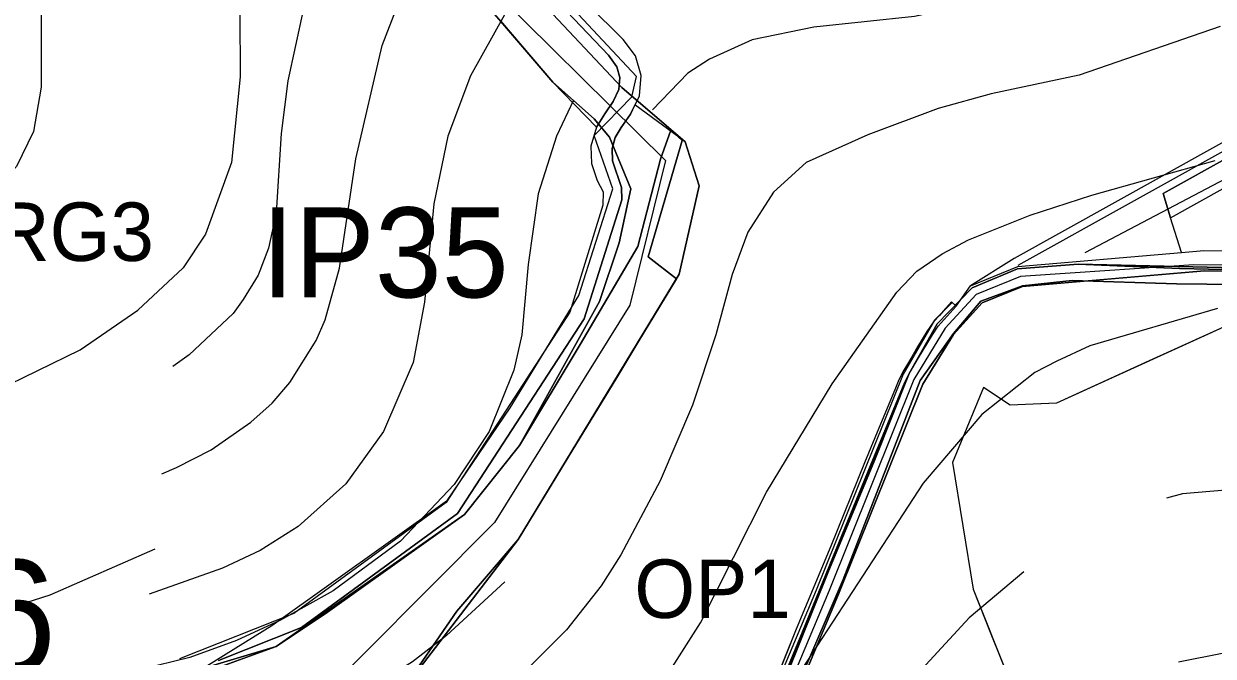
# Model space of a CAD drawing. Extents: x -1900516 to -575031, y -3809306 to -1157387.
# Drawn here: x -579252.3 to -578987.9, y -1159438.2 to -1159297.6 of the extents above; entities that cross this region are included whole.
import ezdxf

# ---------------------------------------------------------------- set-up
doc = ezdxf.new("R2010")
doc.units = 0
for name, color, linetype in [('01_PARCELY_NÁVRH_PC', 7, 'Continuous'), ('01_PARCELY_NÁVRH_VHO', 7, 'Continuous'), ('01_PARCELY_NÁVRH_ŽP', 7, 'Continuous'), ('01_VRSTEVNICE', 7, 'Continuous'), ('02_KULTURY STAV', 7, 'Continuous'), ('03_PC_NÁVRH', 7, 'Continuous'), ('03_PC_OBJEKTY_NÁVRH', 7, 'Continuous'), ('03_PC_POPIS_NÁVRH', 7, 'Continuous'), ('04_ZPF_OP_ORGAN', 7, 'Continuous'), ('05_VHO_PŘÍKOP_NÁVRH', 7, 'Continuous'), ('06_ÚSES_BC', 7, 'Continuous'), ('06_ÚSES_IP', 7, 'Continuous')]:
    doc.layers.add(name, color=color, linetype=linetype)

msp = doc.modelspace()

# ---------------------------------------------------------------- linework, layer by layer
at = {"layer": '01_PARCELY_NÁVRH_PC'}
for points in [[(-579209.05, -1159439.13), (-579190.58, -1159431.78), (-579173.22, -1159419.14), (-579155.86, -1159406.49), (-579127.75, -1159363.22), (-579119.37, -1159336.76), (-579119.42, -1159333.98), (-579121.41, -1159328.05), (-579121.51, -1159325.32), (-579120.84, -1159322.86), (-579119.5, -1159320.68), (-579117.45, -1159317.67), (-579115.47, -1159313.61), (-579115.1, -1159309.07), (-579116.34, -1159304.73), (-579119.1, -1159301.09), (-579150.26, -1159270.13)], [(-579153.05, -1159272.27), (-579122.3, -1159304.59), (-579120.47, -1159307.14), (-579119.83, -1159309.54), (-579120.01, -1159312.2), (-579121.28, -1159314.87), (-579123.13, -1159317.62), (-579125.03, -1159320.58), (-579126.23, -1159324.78), (-579126.14, -1159328.62), (-579124.85, -1159332.45), (-579123.48, -1159334.93), (-579123.57, -1159337.94), (-579130.95, -1159361.72), (-579158.44, -1159404.04), (-579192.28, -1159428.69), (-579217.66, -1159438.78)], [(-578954.52, -1159306.57), (-579032.13, -1159349.74), (-579041.89, -1159355.85), (-579031.32, -1159351.56), (-578994.97, -1159348.41), (-578997.37, -1159340.71), (-578999.05, -1159335.34), (-578952.82, -1159309.63)], [(-579084.53, -1159445.74), (-579079.22, -1159432.79), (-579071.64, -1159414.28), (-579061.79, -1159390.22), (-579056.48, -1159377.27), (-579055.45, -1159375.3), (-579053.4, -1159371.87), (-579052.38, -1159370.15), (-579051.36, -1159368.43), (-579050.33, -1159366.71), (-579049.01, -1159364.85), (-579046.35, -1159361.87), (-579045.01, -1159360.38), (-579041.89, -1159355.85), (-579031.32, -1159351.56), (-578994.97, -1159348.41), (-578990.02, -1159347.98), (-578977.69, -1159348.14)], [(-578680.53, -1159438.83), (-578690.19, -1159436.04), (-578719.21, -1159428.39), (-578740.5, -1159423.22), (-578800.71, -1159407.93), (-578802.57, -1159407.45), (-578816, -1159402.88), (-578834.08, -1159395.96), (-578841.47, -1159393.66), (-578845.51, -1159391.77), (-578865.03, -1159378.15), (-578869.94, -1159374.29), (-578878.12, -1159369.12), (-578887.02, -1159365.74), (-578913.36, -1159358.64), (-578960.86, -1159353.66), (-578977.85, -1159352.64), (-578989.86, -1159352.48), (-579030.26, -1159355.98), (-579039.25, -1159359.63), (-579045.66, -1159366.64), (-579052.43, -1159377.7), (-579071.21, -1159424.42), (-579081.08, -1159447.93)]]:
    msp.add_lwpolyline(points, dxfattribs=at)
at = {"layer": '01_PARCELY_NÁVRH_VHO'}
msp.add_lwpolyline([(-579084.53, -1159445.74), (-579079.22, -1159432.79), (-579071.64, -1159414.28), (-579064.06, -1159395.77), (-579061.79, -1159390.22), (-579056.48, -1159377.27), (-579055.45, -1159375.3), (-579053.4, -1159371.87), (-579052.38, -1159370.15), (-579051.36, -1159368.43), (-579050.33, -1159366.71), (-579049.01, -1159364.85), (-579046.35, -1159361.87), (-579045.01, -1159360.38), (-579046.07, -1159359.44), (-579047.41, -1159360.92), (-579048.75, -1159362.41), (-579050.09, -1159363.89), (-579051.56, -1159365.98), (-579052.58, -1159367.7), (-579053.6, -1159369.42), (-579054.62, -1159371.14), (-579055.64, -1159372.86), (-579056.67, -1159374.58), (-579057.8, -1159376.72), (-579058.56, -1159378.57), (-579063.13, -1159389.67), (-579065.4, -1159395.22), (-579072.92, -1159413.76), (-579080.64, -1159432.21), (-579088.06, -1159450.78)], dxfattribs=at)
at = {"layer": '01_PARCELY_NÁVRH_ŽP'}
msp.add_lwpolyline([(-578999.05, -1159335.34), (-578997.37, -1159340.71), (-578949.92, -1159314.31), (-578911.36, -1159292.87), (-578872.49, -1159271.26), (-578837.52, -1159245.73), (-578815.84, -1159242.76), (-578817.98, -1159237.69), (-578840.76, -1159241.28), (-578875.16, -1159266.45), (-578914.03, -1159288.06), (-578952.82, -1159309.63)], close=True, dxfattribs=at)
for points in [[(-579146.34, -1159296.96), (-579134.7, -1159310.56), (-579125.03, -1159320.58), (-579123.13, -1159317.62), (-579121.28, -1159314.87), (-579120.01, -1159312.2), (-579119.83, -1159309.54), (-579120.47, -1159307.14), (-579122.3, -1159304.59), (-579153.05, -1159272.27)], [(-579169.04, -1159446.99), (-579156.06, -1159428.15), (-579142.39, -1159412.25), (-579120.6, -1159376.58), (-579106.62, -1159353.29), (-579102.18, -1159333.62), (-579105.29, -1159323.85), (-579116.46, -1159315.64), (-579117.45, -1159317.67), (-579119.5, -1159320.68), (-579120.84, -1159322.86), (-579121.51, -1159325.32), (-579121.41, -1159328.05), (-579119.42, -1159333.98), (-579119.37, -1159336.76), (-579127.75, -1159363.22), (-579155.86, -1159406.49), (-579173.22, -1159419.14), (-579190.58, -1159431.78), (-579209.05, -1159439.13)]]:
    msp.add_lwpolyline(points, dxfattribs=at)
at = {"layer": '01_VRSTEVNICE'}
for points in [[(-579204.1, -1159228.9), (-579221.33, -1159241.77), (-579232.52, -1159251.14), (-579240.64, -1159260.23), (-579245.53, -1159268.07), (-579248.47, -1159277.86), (-579248.47, -1159311.71), (-579250.15, -1159321.51), (-579253.93, -1159329.34), (-579260.22, -1159336.2), (-579266.66, -1159340.25), (-579273.37, -1159343.33), (-579295.2, -1159350.74), (-579311.98, -1159357.74), (-579318.42, -1159361.94), (-579338.56, -1159377.74), (-579341.36, -1159379.28), (-579345.56, -1159380.4), (-579352.55, -1159380.4), (-579359.55, -1159378.16), (-579372.7, -1159368.09), (-579383.19, -1159361.24)], [(-579184.51, -1159246.42), (-579188.25, -1159248.59), (-579193.39, -1159254.13), (-579199.03, -1159262.71), (-579202.39, -1159271.38), (-579204.35, -1159280.89), (-579204.21, -1159309.41), (-579206.16, -1159328.43), (-579211.88, -1159344.33), (-579216.89, -1159351.85)], [(-579173.17, -1159262.29), (-579182.11, -1159274.59), (-579190.22, -1159294.59), (-579193.58, -1159310.25), (-579195.12, -1159321.99), (-579196.24, -1159339.61), (-579197.92, -1159347.44), (-579200.23, -1159353.46), (-579203.51, -1159358.91), (-579205.74, -1159361.98), (-579215.53, -1159371.21), (-579219.2, -1159373.8)], [(-578983.57, -1159271.8), (-579008.46, -1159279.21), (-579018.1, -1159283.26), (-579027.75, -1159288.58), (-579038.1, -1159292.49), (-579054.32, -1159295.99), (-579076.69, -1159298.36), (-579090.39, -1159301.16), (-579099.9, -1159305.49), (-579104.66, -1159308.57), (-579112.54, -1159316.69)], [(-579221.59, -1159397.65), (-579218.33, -1159396.24), (-579210.64, -1159392.32), (-579201.83, -1159386.17), (-579197.08, -1159381.94), (-579193.16, -1159377.36), (-579187.29, -1159367.99), (-579185.33, -1159363.38), (-579182.11, -1159351.92), (-579178.48, -1159327.59), (-579172.61, -1159302.42), (-579166.73, -1159287.04), (-579161.56, -1159278.23)], [(-579145.48, -1159295.57), (-579153.03, -1159309.13), (-579158.07, -1159322.55), (-579161.14, -1159337.65), (-579163.24, -1159359.47), (-579165.76, -1159372.89), (-579172.33, -1159388.27), (-579180.72, -1159399.87), (-579191.34, -1159409.38), (-579199.73, -1159414.69), (-579208.12, -1159418.61), (-579224.42, -1159424.38)], [(-578986.37, -1159298.22), (-579017.69, -1159308.99), (-579037.26, -1159313.18), (-579049.01, -1159316.4), (-579064.67, -1159322.27), (-579078.37, -1159328.43), (-579085.64, -1159335), (-579091.37, -1159343.95), (-579094.87, -1159353.31), (-579098.5, -1159366.74), (-579103.68, -1159382.4), (-579110.81, -1159399.17), (-579119.61, -1159415.67), (-579123.95, -1159422.52), (-579131.64, -1159432.31), (-579141.57, -1159442.24)], [(-579130.1, -1159314.58), (-579133.88, -1159322.55), (-579137.93, -1159335.42), (-579140.17, -1159351.08), (-579141.57, -1159366.74), (-579143.39, -1159374.57), (-579148.84, -1159388.27), (-579156.67, -1159400.01), (-579168.55, -1159412.6), (-579183.51, -1159423.64), (-579195.26, -1159430.21), (-579205.05, -1159434.69), (-579215.39, -1159438.46), (-579226.29, -1159441.18)], [(-579113.32, -1159448.67), (-579101.86, -1159430.77), (-579087.18, -1159401.69), (-579072.64, -1159377.64), (-579058.23, -1159357.23), (-579053.76, -1159352.61), (-579048.17, -1159348.7), (-579042.3, -1159345.62), (-579028.59, -1159340.17), (-579014.89, -1159335.7), (-578987.48, -1159328.01)], [(-579382.07, -1159405.16), (-579367.38, -1159417.89), (-579353.95, -1159421.11), (-579344.44, -1159420.97), (-579339.12, -1159420.13), (-579332.13, -1159417.89), (-579303.59, -1159396.91), (-579294.92, -1159392.01), (-579258.68, -1159379.28), (-579239.8, -1159370.05), (-579226.93, -1159361.24), (-579216.89, -1159351.85)], [(-578986.93, -1159360.86), (-579015.33, -1159369.16), (-579022.69, -1159372.61), (-579027.53, -1159375.09), (-579039.36, -1159384.49), (-579052.36, -1159399.73), (-579081.58, -1159444.48)], [(-578771.18, -1159440), (-578778.59, -1159429.38), (-578786.56, -1159419.45), (-578799.84, -1159405.61), (-578804.18, -1159401.99), (-578808.23, -1159399.17), (-578826.13, -1159389.81), (-578839.55, -1159384.07), (-578844.87, -1159383.65), (-578850.45, -1159384.31), (-578855.49, -1159386.03), (-578859.27, -1159388.69), (-578862.62, -1159392.04), (-578875.07, -1159408.54), (-578880.42, -1159413.67), (-578886.81, -1159418.75), (-578899.96, -1159426.02), (-578910.02, -1159428.96), (-578925.12, -1159431.47), (-578970.43, -1159435.53), (-578985.53, -1159437.49), (-578995.61, -1159439.55)], [(-578923.87, -1159399.45), (-578934.91, -1159400.29), (-578968.61, -1159399.87), (-578994.76, -1159402.11), (-578998.25, -1159403.09)], [(-579223.15, -1159414.4), (-579246.51, -1159424.61), (-579290.44, -1159438.6)], [(-579029.99, -1159419.45), (-579042.16, -1159429.66), (-579051.8, -1159440.14), (-579069.84, -1159462.65), (-579085.08, -1159484.04), (-579098.5, -1159499.56), (-579104.93, -1159505.58), (-579119.2, -1159516.48), (-579128.7, -1159522.5), (-579156.39, -1159537.32), (-579166.04, -1159545.01), (-579172.75, -1159551.86), (-579176.8, -1159557.73), (-579180.58, -1159565.56), (-579181.7, -1159569.48), (-579183.09, -1159581.22), (-579182.67, -1159591.01), (-579180.44, -1159610.58), (-579169.67, -1159651.69), (-579166.73, -1159667.35), (-579165.48, -1159692.24), (-579165.9, -1159709.02), (-579168.55, -1159742.15), (-579168.96, -1159747.01)], [(-579145.34, -1159421.69), (-579158.35, -1159433.57), (-579165.9, -1159439.44), (-579182.68, -1159449.93), (-579191.24, -1159454.55), (-579212.26, -1159463.69), (-579229.13, -1159469.44)]]:
    msp.add_lwpolyline(points, dxfattribs=at)
at = {"layer": '02_KULTURY STAV'}
msp.add_lwpolyline([(-579302.73, -1159497.75), (-579267.02, -1159475.41), (-579254.54, -1159463.78), (-579215.76, -1159441.86), (-579196.21, -1159436.02), (-579154.37, -1159406.71), (-579142.11, -1159391.36), (-579128.62, -1159368.88), (-579115.79, -1159347.14), (-579110.76, -1159327.69), (-579108.45, -1159321.21), (-579105.93, -1159323.53), (-579113.49, -1159349.44), (-579107.21, -1159354.26), (-579142.39, -1159412.25), (-579169.04, -1159446.99), (-579192.97, -1159492.55), (-579132.01, -1159545.71), (-579137.13, -1159550.49), (-579168.38, -1159545.06), (-579186.85, -1159536.67), (-579197.58, -1159531.38), (-579208.3, -1159526.1), (-579287.54, -1159501.52)], close=True, dxfattribs=at)
for points in [[(-579169.04, -1159446.99), (-579142.39, -1159412.25), (-579107.21, -1159354.26), (-579113.49, -1159349.44), (-579105.93, -1159323.53), (-579108.45, -1159321.21), (-579110.76, -1159327.69), (-579115.79, -1159347.14), (-579128.62, -1159368.88), (-579142.11, -1159391.36), (-579154.37, -1159406.71), (-579196.21, -1159436.02), (-579215.76, -1159441.86)], [(-578976.03, -1159352.43), (-578995.36, -1159351.99), (-579017.93, -1159351.06), (-579031.38, -1159352.1), (-579041.47, -1159356.26), (-579049.25, -1159364.29), (-579055.48, -1159375.32), (-579063.21, -1159394.68), (-579073.57, -1159419.63), (-579082.5, -1159441.98)], [(-579082.5, -1159441.98), (-579073.57, -1159419.63), (-579063.21, -1159394.68), (-579055.48, -1159375.32), (-579049.25, -1159364.29), (-579041.47, -1159356.26), (-579031.38, -1159352.1), (-579017.93, -1159351.06), (-578995.36, -1159351.99), (-578976.03, -1159352.43)], [(-578975.87, -1159355.65), (-578996.07, -1159355.4), (-579019.22, -1159354.68), (-579030.33, -1159355.88), (-579039.56, -1159359.28), (-579045.67, -1159366.44), (-579053.05, -1159376.92), (-579070.19, -1159421.12), (-579079.83, -1159443.56)], [(-579079.83, -1159443.56), (-579070.19, -1159421.12), (-579053.05, -1159376.92), (-579045.67, -1159366.44), (-579039.56, -1159359.28), (-579030.33, -1159355.88), (-579019.22, -1159354.68), (-578996.07, -1159355.4), (-578975.87, -1159355.65)], [(-578919.48, -1159440.16), (-578896.76, -1159437.65), (-578874.05, -1159435.14), (-578864.96, -1159429.74), (-578859.11, -1159416.39), (-578853.26, -1159403.04), (-578851.7, -1159388.13), (-578885.91, -1159374.98), (-578911.16, -1159364.65), (-578932.04, -1159361.7), (-578956.78, -1159362.44), (-578981.52, -1159363.18), (-579002.12, -1159372.56), (-579022.72, -1159381.94), (-579027.89, -1159382.17), (-579033.06, -1159382.4), (-579038.97, -1159378.47), (-579045.87, -1159395.1), (-579043.56, -1159409.18), (-579041.24, -1159423.26), (-579037.3, -1159433.19), (-579033.36, -1159443.12)], [(-578981.52, -1159363.18), (-579022.72, -1159381.94), (-579033.06, -1159382.4), (-579038.97, -1159378.47), (-579045.87, -1159395.1), (-579041.24, -1159423.26), (-579033.36, -1159443.12)]]:
    msp.add_lwpolyline(points, dxfattribs=at)
at = {"layer": '03_PC_NÁVRH'}
for points in [[(-579215.95, -1159443), (-579197.17, -1159431.39), (-579158.1, -1159403.48), (-579144.16, -1159382.97), (-579128.89, -1159358.02), (-579121.35, -1159334.32), (-579125.5, -1159322.44), (-579117.12, -1159313.8), (-579116.13, -1159309.29), (-579151.57, -1159271.29), (-579158.84, -1159254.47), (-579157.24, -1159244.6), (-579150.76, -1159236.03), (-579103.57, -1159230.86), (-579083.6, -1159225.15), (-579037.45, -1159215.89), (-578997.46, -1159192.24), (-578970.28, -1159164.33), (-578956.73, -1159145.48), (-578959.93, -1159136.11), (-578969.35, -1159116.37), (-578974.34, -1159098.37), (-578973.86, -1159084.91)], [(-579031.28, -1159351.27), (-578876.06, -1159264.94), (-578841.47, -1159239.63), (-578766.48, -1159226.28)], [(-578664.08, -1159439.49), (-578691.06, -1159433.13), (-578731.31, -1159423.24), (-578788.51, -1159407.98), (-578818.79, -1159399.62), (-578840.13, -1159391.55), (-578863.75, -1159376.3), (-578876.23, -1159367.7), (-578904.71, -1159359.13), (-578912.91, -1159356.43), (-578932.04, -1159354.63), (-578960.73, -1159351.41), (-578992.19, -1159351.2), (-579018.62, -1159352.98), (-579030.77, -1159353.76), (-579040.57, -1159357.74), (-579047.47, -1159365.28), (-579054.45, -1159376.69), (-579073.29, -1159423.57), (-579083.15, -1159447.06)]]:
    msp.add_lwpolyline(points, dxfattribs=at)
at = {"layer": '03_PC_OBJEKTY_NÁVRH'}
msp.add_lwpolyline([(-579046.04, -1159359.62), (-579049.84, -1159363.49), (-579056.82, -1159375.5), (-579076.14, -1159423.5), (-579105.96, -1159494.48), (-579118.99, -1159519), (-579134.83, -1159551.4)], dxfattribs=at)
at = {"layer": '04_ZPF_OP_ORGAN'}
for points in [[(-579169.04, -1159446.99), (-579156.06, -1159428.15), (-579142.39, -1159412.25), (-579106.62, -1159353.29), (-579102.18, -1159333.62), (-579105.29, -1159323.85), (-579119.37, -1159311.73), (-579153.61, -1159275.3), (-579162.99, -1159257.22), (-579163.07, -1159246.17), (-579159.59, -1159238.72), (-579154.08, -1159231.75), (-579146.75, -1159230.03), (-579125.73, -1159228.22), (-579108.84, -1159225.82), (-579038.48, -1159211.55), (-579003.06, -1159190.63), (-578987.06, -1159176.18)], [(-578987.06, -1159176.18), (-579003.06, -1159190.63), (-579038.48, -1159211.55), (-579108.84, -1159225.82), (-579125.73, -1159228.22), (-579146.75, -1159230.03), (-579154.08, -1159231.75), (-579159.59, -1159238.72), (-579163.07, -1159246.17), (-579162.99, -1159257.22), (-579153.61, -1159275.3), (-579119.37, -1159311.73), (-579105.29, -1159323.85), (-579102.18, -1159333.62), (-579106.62, -1159353.29), (-579142.39, -1159412.25), (-579156.06, -1159428.15), (-579169.04, -1159446.99)], [(-579254.54, -1159463.78), (-579235.89, -1159452.25), (-579217.79, -1159443.43), (-579214.11, -1159442.56), (-579196.21, -1159436.02), (-579185.3, -1159428.79), (-579154.37, -1159406.71), (-579142.11, -1159391.36), (-579124.32, -1159359.32), (-579119.98, -1159346.29), (-579117.4, -1159334.25), (-579122.08, -1159322.8), (-579125.48, -1159318.76), (-579134.7, -1159310.56), (-579159.22, -1159281.9), (-579175.45, -1159252.63), (-579182.99, -1159242.55), (-579196.86, -1159234.31), (-579207.91, -1159233.24), (-579215.14, -1159234.78), (-579244.2, -1159240.96), (-579278.25, -1159242.89)], [(-579278.25, -1159242.89), (-579244.2, -1159240.96), (-579215.14, -1159234.78), (-579207.91, -1159233.24), (-579196.86, -1159234.31), (-579182.99, -1159242.55), (-579175.45, -1159252.63), (-579159.22, -1159281.9), (-579134.7, -1159310.56), (-579125.48, -1159318.76), (-579122.08, -1159322.8), (-579117.4, -1159334.25), (-579119.98, -1159346.29), (-579124.32, -1159359.32), (-579142.11, -1159391.36), (-579154.37, -1159406.71), (-579185.3, -1159428.79), (-579196.21, -1159436.02), (-579214.11, -1159442.56), (-579217.79, -1159443.43), (-579235.89, -1159452.25), (-579254.54, -1159463.78)], [(-578947.72, -1159352.64), (-579017.93, -1159351.06), (-579031.38, -1159352.1), (-579041.47, -1159356.26), (-579049.25, -1159364.29), (-579055.48, -1159375.32), (-579084.94, -1159446.94)], [(-579084.94, -1159446.94), (-579055.48, -1159375.32), (-579049.25, -1159364.29), (-579041.47, -1159356.26), (-579031.38, -1159352.1), (-579017.93, -1159351.06), (-578947.72, -1159352.64)]]:
    msp.add_lwpolyline(points, dxfattribs=at)
at = {"layer": '05_VHO_PŘÍKOP_NÁVRH'}
for p, q in [((-579046.07, -1159359.44), (-579047.41, -1159360.92)), ((-579046.35, -1159361.87), (-579045.01, -1159360.38)), ((-579045.01, -1159360.38), (-579046.07, -1159359.44)), ((-579048.75, -1159362.41), (-579050.09, -1159363.89)), ((-579049.01, -1159364.85), (-579046.35, -1159361.87)), ((-579047.41, -1159360.92), (-579048.75, -1159362.41)), ((-579051.56, -1159365.98), (-579052.58, -1159367.7)), ((-579050.09, -1159363.89), (-579051.56, -1159365.98)), ((-579050.33, -1159366.71), (-579049.01, -1159364.85)), ((-579052.58, -1159367.7), (-579053.6, -1159369.42)), ((-579052.38, -1159370.15), (-579051.36, -1159368.43)), ((-579051.36, -1159368.43), (-579050.33, -1159366.71)), ((-579054.62, -1159371.14), (-579055.64, -1159372.86)), ((-579053.6, -1159369.42), (-579054.62, -1159371.14)), ((-579053.4, -1159371.87), (-579052.38, -1159370.15)), ((-579055.64, -1159372.86), (-579056.67, -1159374.58)), ((-579055.45, -1159375.3), (-579053.4, -1159371.87)), ((-579056.67, -1159374.58), (-579057.8, -1159376.72)), ((-579056.48, -1159377.27), (-579055.45, -1159375.3)), ((-579058.56, -1159378.57), (-579063.13, -1159389.67)), ((-579061.79, -1159390.22), (-579056.48, -1159377.27)), ((-579057.8, -1159376.72), (-579058.56, -1159378.57)), ((-579063.13, -1159389.67), (-579065.4, -1159395.22)), ((-579071.64, -1159414.28), (-579061.79, -1159390.22)), ((-579065.4, -1159395.22), (-579072.92, -1159413.76)), ((-579072.92, -1159413.76), (-579080.64, -1159432.21)), ((-579079.22, -1159432.79), (-579071.64, -1159414.28)), ((-579080.64, -1159432.21), (-579088.06, -1159450.78)), ((-579084.53, -1159445.74), (-579079.22, -1159432.79))]:
    msp.add_line(p, q, dxfattribs=at)
at = {"layer": '06_ÚSES_BC'}
msp.add_line((-579039.25, -1159359.63), (-579030.26, -1159355.98), dxfattribs=at)
for points in [[(-579030.26, -1159355.98), (-579018.4, -1159354.96), (-578989.86, -1159352.48), (-578977.85, -1159352.64)], [(-579052.43, -1159377.7), (-579045.66, -1159366.64), (-579039.25, -1159359.63)], [(-579071.21, -1159424.42), (-579052.43, -1159377.7)], [(-579097.48, -1159486.7), (-579081.08, -1159447.93), (-579071.21, -1159424.42)]]:
    msp.add_lwpolyline(points, dxfattribs=at)
at = {"layer": '06_ÚSES_IP'}
for points in [[(-579176.37, -1159235.29), (-579153.27, -1159284.79), (-579109.65, -1159327.99), (-579117.56, -1159360.12), (-579147.69, -1159408.49), (-579191.14, -1159452.15), (-579205.53, -1159462.14)], [(-579016.36, -1159348.46), (-578871.46, -1159272.11), (-578829.42, -1159241.15), (-578810.66, -1159239.61)]]:
    msp.add_lwpolyline(points, dxfattribs=at)

# ---------------------------------------------------------------- texts
at = {"layer": '03_PC_OBJEKTY_NÁVRH'}
msp.add_text('OP1', height=13, dxfattribs=at).set_placement((-579116.58, -1159429.69))
at = {"layer": '03_PC_POPIS_NÁVRH'}
msp.add_text('DC36', height=25, dxfattribs=at).set_placement((-579330.56, -1159441.8))
at = {"layer": '04_ZPF_OP_ORGAN'}
msp.add_text('ORG3', height=13, dxfattribs=at).set_placement((-579272.64, -1159350.32))
at = {"layer": '06_ÚSES_IP'}
msp.add_text('IP35', height=20, dxfattribs=at).set_placement((-579199.54, -1159358.42))

doc.saveas('drawing.dxf')
